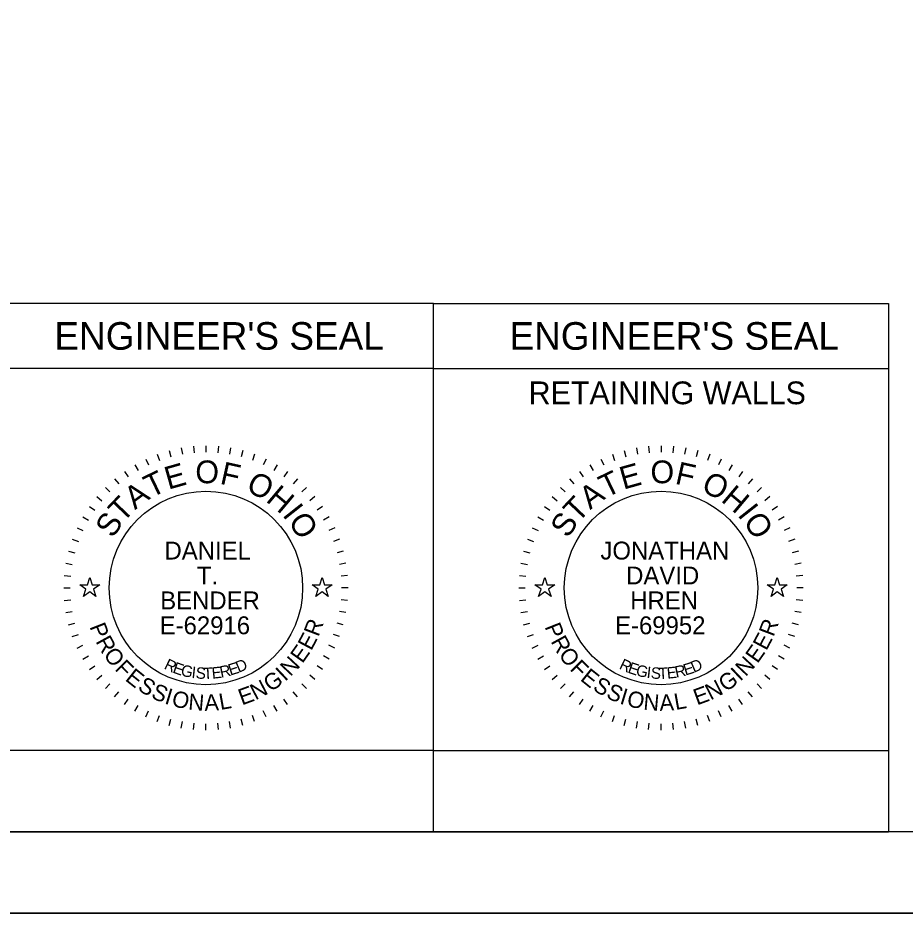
# Model space of a CAD drawing. Extents: x 0 to 44.3, y 0 to 22.
# Drawn here: x 23.84 to 29.3, y 0 to 5.51 of the extents above; entities that cross this region are included whole.
import ezdxf

# ---------------------------------------------------------------- set-up
doc = ezdxf.new("R2010")
doc.units = 0
for name, color, linetype in [('Default', 7, 'Continuous'), ('SH_Border', 7, 'Continuous'), ('SH_Cut_Line', 7, 'Continuous'), ('SH_Data', 7, 'Continuous')]:
    doc.layers.add(name, color=color, linetype=linetype)

msp = doc.modelspace()

# ---------------------------------------------------------------- linework, layer by layer
at = {"layer": 'Default'}
for points in [[(24.2236, 2.02), (24.2705, 2.02), (24.285, 2.0645), (24.2995, 2.02), (24.3464, 2.02), (24.3085, 1.9924), (24.323, 1.9478), (24.285, 1.9754), (24.247, 1.9478), (24.2615, 1.9924)], [(25.6536, 2.02), (25.7005, 2.02), (25.715, 2.0645), (25.7295, 2.02), (25.7764, 2.02), (25.7385, 1.9924), (25.753, 1.9478), (25.715, 1.9754), (25.677, 1.9478), (25.6915, 1.9924)], [(27.0236, 2.02), (27.0705, 2.02), (27.085, 2.0645), (27.0995, 2.02), (27.1464, 2.02), (27.1085, 1.9924), (27.123, 1.9478), (27.085, 1.9754), (27.047, 1.9478), (27.0615, 1.9924)], [(28.4536, 2.02), (28.5005, 2.02), (28.515, 2.0645), (28.5295, 2.02), (28.5764, 2.02), (28.5385, 1.9924), (28.553, 1.9478), (28.515, 1.9754), (28.477, 1.9478), (28.4915, 1.9924)]]:
    msp.add_lwpolyline(points, close=True, dxfattribs=at)
at = {"layer": 'SH_Border'}
msp.add_lwpolyline([(1.5, 21.5), (33.5, 21.5), (33.5, 0.5), (1.5, 0.5)], close=True, dxfattribs=at)
at = {"layer": 'SH_Cut_Line'}
for points in [[(0, 0), (34, 0), (34, 22), (0, 22)], [(0, 22), (34, 22), (34, 0), (0, 0)]]:
    msp.add_lwpolyline(points, close=True, dxfattribs=at)
at = {"layer": 'SH_Data'}
for p, q in [((26.4, 3.75), (23.6, 3.75)), ((26.4, 0.5), (26.4, 3.75)), ((26.4, 0.5), (26.4, 3.75)), ((26.4, 3.75), (29.2, 3.75)), ((29.2, 3.75), (29.2, 0.5)), ((26.4, 3.35), (23.6, 3.35)), ((26.4, 3.35), (29.2, 3.35)), ((24.9237, 2.8717), (24.9272, 2.8318)), ((25, 2.875), (25, 2.835)), ((25.0763, 2.8717), (25.0728, 2.8318)), ((27.7237, 2.8717), (27.7272, 2.8318)), ((27.8, 2.875), (27.8, 2.835)), ((27.8763, 2.8717), (27.8728, 2.8318)), ((24.7007, 2.8222), (24.7144, 2.7846)), ((24.7735, 2.8452), (24.7839, 2.8065)), ((24.8481, 2.8617), (24.855, 2.8223)), ((25.1519, 2.8617), (25.145, 2.8223)), ((25.2265, 2.8452), (25.2161, 2.8065)), ((25.2993, 2.8222), (25.2856, 2.7846)), ((27.5007, 2.8222), (27.5144, 2.7846)), ((27.5735, 2.8452), (27.5839, 2.8065)), ((27.6481, 2.8617), (27.655, 2.8223)), ((27.9519, 2.8617), (27.945, 2.8223)), ((28.0265, 2.8452), (28.0161, 2.8065)), ((28.0993, 2.8222), (28.0856, 2.7846)), ((24.5625, 2.7578), (24.5825, 2.7231)), ((24.6302, 2.793), (24.6471, 2.7568)), ((25.3698, 2.793), (25.3529, 2.7568)), ((25.4375, 2.7578), (25.4175, 2.7231)), ((27.3625, 2.7578), (27.3825, 2.7231)), ((27.4302, 2.793), (27.4471, 2.7568)), ((28.1698, 2.793), (28.1529, 2.7568)), ((28.2375, 2.7578), (28.2175, 2.7231)), ((24.4981, 2.7168), (24.5211, 2.684)), ((25.5019, 2.7168), (25.4789, 2.684)), ((27.2981, 2.7168), (27.3211, 2.684)), ((28.3019, 2.7168), (28.2789, 2.684)), ((24.4376, 2.6703), (24.4633, 2.6396)), ((25.5624, 2.6703), (25.5367, 2.6396)), ((27.2376, 2.6703), (27.2633, 2.6396)), ((28.3624, 2.6703), (28.3367, 2.6396)), ((24.3813, 2.6187), (24.4096, 2.5904)), ((25.6187, 2.6187), (25.5904, 2.5904)), ((27.1813, 2.6187), (27.2096, 2.5904)), ((28.4187, 2.6187), (28.3904, 2.5904)), ((24.3297, 2.5624), (24.3604, 2.5367)), ((25.6703, 2.5624), (25.6396, 2.5367)), ((27.1297, 2.5624), (27.1604, 2.5367)), ((28.4703, 2.5624), (28.4396, 2.5367)), ((24.2832, 2.5019), (24.316, 2.4789)), ((25.7168, 2.5019), (25.684, 2.4789)), ((27.0832, 2.5019), (27.116, 2.4789)), ((28.5168, 2.5019), (28.484, 2.4789)), ((24.2422, 2.4375), (24.2769, 2.4175)), ((25.7578, 2.4375), (25.7231, 2.4175)), ((27.0422, 2.4375), (27.0769, 2.4175)), ((28.5578, 2.4375), (28.5231, 2.4175)), ((24.207, 2.3698), (24.2432, 2.3529)), ((25.793, 2.3698), (25.7568, 2.3529)), ((27.007, 2.3698), (27.0432, 2.3529)), ((28.593, 2.3698), (28.5568, 2.3529)), ((24.1778, 2.2993), (24.2154, 2.2856)), ((25.8222, 2.2993), (25.7846, 2.2856)), ((26.9778, 2.2993), (27.0154, 2.2856)), ((28.6222, 2.2993), (28.5846, 2.2856)), ((24.1548, 2.2265), (24.1935, 2.2161)), ((25.8452, 2.2265), (25.8065, 2.2161)), ((26.9548, 2.2265), (26.9935, 2.2161)), ((28.6452, 2.2265), (28.6065, 2.2161)), ((24.1383, 2.1519), (24.1777, 2.145)), ((25.8617, 2.1519), (25.8223, 2.145)), ((26.9383, 2.1519), (26.9777, 2.145)), ((28.6617, 2.1519), (28.6223, 2.145)), ((24.1283, 2.0763), (24.1682, 2.0728)), ((25.8717, 2.0763), (25.8318, 2.0728)), ((26.9283, 2.0763), (26.9682, 2.0728)), ((28.6717, 2.0763), (28.6318, 2.0728)), ((24.125, 2), (24.165, 2)), ((25.875, 2), (25.835, 2)), ((26.925, 2), (26.965, 2)), ((28.675, 2), (28.635, 2)), ((24.1283, 1.9237), (24.1682, 1.9272)), ((25.8717, 1.9237), (25.8318, 1.9272)), ((26.9283, 1.9237), (26.9682, 1.9272)), ((28.6717, 1.9237), (28.6318, 1.9272)), ((24.1383, 1.8481), (24.1777, 1.855)), ((25.8617, 1.8481), (25.8223, 1.855)), ((26.9383, 1.8481), (26.9777, 1.855)), ((28.6617, 1.8481), (28.6223, 1.855)), ((24.1548, 1.7735), (24.1935, 1.7839)), ((25.8452, 1.7735), (25.8065, 1.7839)), ((26.9548, 1.7735), (26.9935, 1.7839)), ((28.6452, 1.7735), (28.6065, 1.7839)), ((24.1778, 1.7007), (24.2154, 1.7144)), ((25.8222, 1.7007), (25.7846, 1.7144)), ((26.9778, 1.7007), (27.0154, 1.7144)), ((28.6222, 1.7007), (28.5846, 1.7144)), ((24.207, 1.6302), (24.2432, 1.6471)), ((25.793, 1.6302), (25.7568, 1.6471)), ((27.007, 1.6302), (27.0432, 1.6471)), ((28.593, 1.6302), (28.5568, 1.6471)), ((24.2422, 1.5625), (24.2769, 1.5825)), ((25.7578, 1.5625), (25.7231, 1.5825)), ((27.0422, 1.5625), (27.0769, 1.5825)), ((28.5578, 1.5625), (28.5231, 1.5825)), ((24.2832, 1.4981), (24.316, 1.5211)), ((25.7168, 1.4981), (25.684, 1.5211)), ((27.0832, 1.4981), (27.116, 1.5211)), ((28.5168, 1.4981), (28.484, 1.5211)), ((24.3297, 1.4376), (24.3604, 1.4633)), ((25.6703, 1.4376), (25.6396, 1.4633)), ((27.1297, 1.4376), (27.1604, 1.4633)), ((28.4703, 1.4376), (28.4396, 1.4633)), ((24.3813, 1.3813), (24.4096, 1.4096)), ((25.6187, 1.3813), (25.5904, 1.4096)), ((27.1813, 1.3813), (27.2096, 1.4096)), ((28.4187, 1.3813), (28.3904, 1.4096)), ((24.4376, 1.3297), (24.4633, 1.3604)), ((25.5624, 1.3297), (25.5367, 1.3604)), ((27.2376, 1.3297), (27.2633, 1.3604)), ((28.3624, 1.3297), (28.3367, 1.3604)), ((24.4981, 1.2832), (24.5211, 1.316)), ((24.5625, 1.2422), (24.5825, 1.2769)), ((25.4375, 1.2422), (25.4175, 1.2769)), ((25.5019, 1.2832), (25.4789, 1.316)), ((27.2981, 1.2832), (27.3211, 1.316)), ((27.3625, 1.2422), (27.3825, 1.2769)), ((28.2375, 1.2422), (28.2175, 1.2769)), ((28.3019, 1.2832), (28.2789, 1.316)), ((24.6302, 1.207), (24.6471, 1.2432)), ((24.7007, 1.1778), (24.7144, 1.2154)), ((25.2993, 1.1778), (25.2856, 1.2154)), ((25.3698, 1.207), (25.3529, 1.2432)), ((27.4302, 1.207), (27.4471, 1.2432)), ((27.5007, 1.1778), (27.5144, 1.2154)), ((28.0993, 1.1778), (28.0856, 1.2154)), ((28.1698, 1.207), (28.1529, 1.2432)), ((24.7735, 1.1548), (24.7839, 1.1935)), ((24.8481, 1.1383), (24.855, 1.1777)), ((24.9237, 1.1283), (24.9272, 1.1682)), ((25, 1.125), (25, 1.165)), ((25.0763, 1.1283), (25.0728, 1.1682)), ((25.1519, 1.1383), (25.145, 1.1777)), ((25.2265, 1.1548), (25.2161, 1.1935)), ((27.5735, 1.1548), (27.5839, 1.1935)), ((27.6481, 1.1383), (27.655, 1.1777)), ((27.7237, 1.1283), (27.7272, 1.1682)), ((27.8, 1.125), (27.8, 1.165)), ((27.8763, 1.1283), (27.8728, 1.1682)), ((27.9519, 1.1383), (27.945, 1.1777)), ((28.0265, 1.1548), (28.0161, 1.1935)), ((26.4, 0.5), (23.6, 0.5)), ((26.4, 0.5), (29.2, 0.5))]:
    msp.add_line(p, q, dxfattribs=at)
for points in [[(26.4, 0.5), (26.4, 1), (23.6, 1), (23.6, 0.5)], [(26.4, 0.5), (26.4, 1), (29.2, 1), (29.2, 0.5)]]:
    msp.add_lwpolyline(points, close=True, dxfattribs=at)
for centre in [(25, 2), (27.8, 2)]:
    msp.add_circle(centre, 0.595, dxfattribs=at)

# ---------------------------------------------------------------- texts
for s, height, p in [("ENGINEER'S SEAL", 0.17, (24.0676, 3.465)), ("ENGINEER'S SEAL", 0.17, (26.8676, 3.465)), ('RETAINING WALLS', 0.14, (26.9852, 3.13)), ('DANIEL', 0.11, (24.7451, 2.1749)), ('JONATHAN', 0.11, (27.4271, 2.1749)), ('T.', 0.11, (24.9439, 2.0216)), ('DAVID', 0.11, (27.5854, 2.0216)), ('BENDER', 0.11, (24.7188, 1.8684)), ('HREN', 0.11, (27.6106, 1.8684)), ('E-62916', 0.11, (24.7154, 1.7151)), ('E-69952', 0.11, (27.5172, 1.7151))]:
    msp.add_text(s, height=height, dxfattribs=at).set_placement(p)
for s, height, rotation, p in [('E', 0.14, 15.7571, (24.7684, 2.6038)), ('O', 0.14, 359.7812, (24.9347, 2.6443)), ('F', 0.14, 347.4362, (25.0811, 2.6417)), ('E', 0.14, 15.7571, (27.5684, 2.6038)), ('O', 0.14, 359.7812, (27.7347, 2.6443)), ('F', 0.14, 347.4362, (27.8811, 2.6417)), ('T', 0.14, 25.7167, (24.6616, 2.5518)), ('O', 0.14, 332.2586, (25.2398, 2.6015)), ('T', 0.14, 25.7167, (27.4616, 2.5518)), ('O', 0.14, 332.2586, (28.0398, 2.6015)), ('A', 0.14, 36.4747, (24.5634, 2.4781)), ('H', 0.14, 319.9136, (25.3632, 2.5361)), ('A', 0.14, 36.4747, (27.3634, 2.4781)), ('H', 0.14, 319.9136, (28.1632, 2.5361)), ('T', 0.14, 46.4344, (24.4883, 2.3964)), ('T', 0.14, 46.4344, (27.2883, 2.3964)), ('I', 0.14, 308.367, (25.4665, 2.4483)), ('I', 0.14, 308.367, (28.2665, 2.4483)), ('S', 0.14, 57.1924, (24.4281, 2.3014)), ('O', 0.14, 303.1491, (25.5021, 2.4089)), ('S', 0.14, 57.1924, (27.2281, 2.3014)), ('O', 0.14, 303.1491, (28.3021, 2.4089)), ('P', 0.1, 291.494, (24.2823, 1.7621)), ('R', 0.1, 69.2322, (25.6919, 1.6954)), ('P', 0.1, 291.494, (27.0823, 1.7621)), ('R', 0.1, 69.2322, (28.4919, 1.6954)), ('R', 0.1, 298.7311, (24.319, 1.6717)), ('E', 0.1, 61.9951, (25.6476, 1.6098)), ('R', 0.1, 298.7311, (27.119, 1.6717)), ('E', 0.1, 61.9951, (28.4476, 1.6098)), ('E', 0.1, 54.758, (25.5933, 1.5314)), ('E', 0.1, 54.758, (28.3933, 1.5314)), ('O', 0.1, 306.4666, (24.3655, 1.5883)), ('O', 0.1, 306.4666, (27.1655, 1.5883)), ('F', 0.1, 314.7068, (24.4343, 1.4983)), ('R', 0.07, 334.487, (24.7375, 1.5051)), ('E', 0.07, 341.04, (24.7906, 1.4801)), ('E', 0.07, 17.6836, (25.1498, 1.4602)), ('D', 0.07, 23.3052, (25.201, 1.477)), ('N', 0.1, 47.0224, (25.5202, 1.4508)), ('F', 0.1, 314.7068, (27.2343, 1.4983)), ('R', 0.07, 334.487, (27.5375, 1.5051)), ('E', 0.07, 341.04, (27.5906, 1.4801)), ('E', 0.07, 17.6836, (27.9498, 1.4602)), ('D', 0.07, 23.3052, (28.001, 1.477)), ('N', 0.1, 47.0224, (28.3202, 1.4508)), ('E', 0.1, 321.4393, (24.4978, 1.4348)), ('G', 0.07, 347.4752, (24.8414, 1.4618)), ('I', 0.07, 353.7858, (24.9091, 1.4468)), ('S', 0.07, 356.8926, (24.9358, 1.4429)), ('T', 0.07, 3.0061, (24.9857, 1.4387)), ('E', 0.07, 6.0117, (25.0389, 1.4412)), ('R', 0.07, 11.9184, (25.0925, 1.4474)), ('I', 0.1, 43.287, (25.4868, 1.4214)), ('E', 0.1, 321.4393, (27.2978, 1.4348)), ('G', 0.07, 347.4752, (27.6414, 1.4618)), ('I', 0.07, 353.7858, (27.7091, 1.4468)), ('S', 0.07, 356.8926, (27.7358, 1.4429)), ('T', 0.07, 3.0061, (27.7857, 1.4387)), ('E', 0.07, 6.0117, (27.8389, 1.4412)), ('R', 0.07, 11.9184, (27.8925, 1.4474)), ('I', 0.1, 43.287, (28.2868, 1.4214)), ('S', 0.1, 328.6764, (24.5743, 1.3752)), ('N', 0.1, 27.3113, (25.3045, 1.3075)), ('G', 0.1, 35.0469, (25.3981, 1.357)), ('S', 0.1, 328.6764, (27.3743, 1.3752)), ('N', 0.1, 27.3113, (28.1045, 1.3075)), ('G', 0.1, 35.0469, (28.1981, 1.357)), ('S', 0.1, 335.9134, (24.6564, 1.3266)), ('I', 0.1, 343.1505, (24.7406, 1.2897)), ('E', 0.1, 20.0742, (25.2212, 1.277)), ('S', 0.1, 335.9134, (27.4564, 1.3266)), ('I', 0.1, 343.1505, (27.5406, 1.2897)), ('E', 0.1, 20.0742, (28.0212, 1.277)), ('O', 0.1, 346.8859, (24.7839, 1.2751)), ('N', 0.1, 355.1261, (24.8888, 1.2517)), ('A', 0.1, 2.8617, (24.9923, 1.2437)), ('L', 0.1, 10.0987, (25.0894, 1.249)), ('O', 0.1, 346.8859, (27.5839, 1.2751)), ('N', 0.1, 355.1261, (27.6888, 1.2517)), ('A', 0.1, 2.8617, (27.7923, 1.2437)), ('L', 0.1, 10.0987, (27.8894, 1.249))]:
    msp.add_text(s, height=height, rotation=rotation, dxfattribs=at).set_placement(p)

doc.saveas('drawing.dxf')
